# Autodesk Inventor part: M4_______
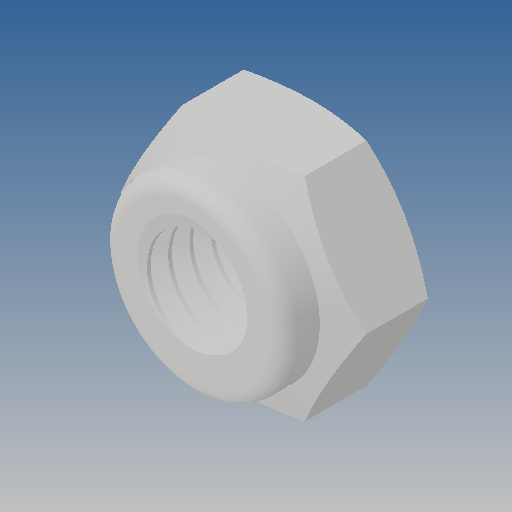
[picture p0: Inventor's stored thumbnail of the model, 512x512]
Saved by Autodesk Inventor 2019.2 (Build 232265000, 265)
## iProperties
Created: 2010-06
Part Number: M4_______
Material: Ogólny
Document SubType Name: Modeling
Designer: CADENGINEERING4
Density: 1 g/cm^3
Appearance: Domyślna
Author: CADENGINEERING4
Revision Number: ANY
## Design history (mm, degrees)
feature "NONE"
node "Bryła1"
